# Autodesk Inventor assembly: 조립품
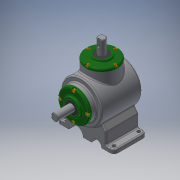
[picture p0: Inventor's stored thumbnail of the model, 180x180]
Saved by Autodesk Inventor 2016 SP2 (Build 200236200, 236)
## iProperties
Created: 2018-08
Part Number: 조립품
Document SubType Name: Assembly
Designer: Administrator
Author: Administrator
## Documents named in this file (14)
- Z:\ATC마스터자격증시험\480807V1027 이상규(인벤터)\조립품.iam
- Z:\ATC마스터자격증시험\480807V1027 이상규(인벤터)\본체.ipt
- Z:\ATC마스터자격증시험\480807V1027 이상규(인벤터)\메인 베벨기어.ipt
- Z:\ATC마스터자격증시험\480807V1027 이상규(인벤터)\메인 축.ipt
- 메인 축.ipt
- Z:\ATC마스터자격증시험\480807V1027 이상규(인벤터)\베어링 6203.ipt
- Z:\ATC마스터자격증시험\480807V1027 이상규(인벤터)\오일실 17 32 8.ipt
- Z:\ATC마스터자격증시험\480807V1027 이상규(인벤터)\커버.ipt
- Z:\ATC마스터자격증시험\480807V1027 이상규(인벤터)\키 5x5.ipt
- Z:\ATC마스터자격증시험\480807V1027 이상규(인벤터)\서브 베벨기어.ipt
- Z:\ATC마스터자격증시험\480807V1027 이상규(인벤터)\서브 축.ipt
- 서브 축.ipt
- Z:\ATC마스터자격증시험\480807V1027 이상규(인벤터)\키 4x4.ipt
- Z:\ATC마스터자격증시험\480807V1027 이상규(인벤터)\볼트 M4.ipt
